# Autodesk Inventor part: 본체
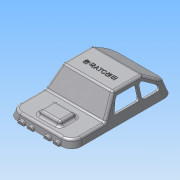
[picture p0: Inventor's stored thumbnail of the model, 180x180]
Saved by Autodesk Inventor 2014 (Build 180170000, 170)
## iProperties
Created: 2015-05
Part Number: 본체
Material: ABS 플라스틱
Document SubType Name: Modeling
Designer: Administrator
Density: 1.06 g/cm^3
Appearance: 매끄러움 - 흰색
Mass: 31 g
Surface Area: 297.951 cm^2
Volume: 29.2452 cm^3
Author: Administrator
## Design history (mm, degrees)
sketch "스케치1"
  geometry: 1 further point
sketch "스케치2"
  geometry: L1 (-61, -38)-(61, -38); L2 (61, -38)-(61, 38); L3 (61, 38)-(-61, 38); L4 (-61, 38)-(-61, -38); L5 (-61, -38)-(61, 38); L6 (61, -38)-(-61, 38); 1 further point
  constraints: 12 end point, 2 midpoint, 2 parallel, 1 horizontal, 1 perpendicular
  dimensions: "d0" = 122 distance of L2.end L3.end; "d1" = 76 distance of L1.end L2.end
extrude "돌출1" new body sketch "스케치2" distance "d2" = 30; taper "d3" = -15 deg
fillet "모깎기1" dims "d4" = 12
sketch "스케치3"
  geometry: L1 (31, 30)-(63.58, 8.28); L2 (41.37, 30)-(52.962, 30) reference; L3 (-41.37, 30)-(41.37, 30) reference; L4 (31, 30)-(52.962, 30); L5 (61, 0)-(49.409, 0) reference; L6 (61, 0)-(61, 30.779); L7 (52.962, 30)-(61, 0) reference; L8 (52.962, 30)-(57.738, 12.175); L9 (52.962, 30)-(57.738, 12.175); 2 further points
  constraints: 10 end point, 4 point on line, 3 collinear, 1 coincident, 1 perpendicular
  dimensions: "d45" = 20 distance from line of L3 point (61, 10); "d53" = 30 horizontal distance of L1.start L5.start
extrude "돌출2" cut sketch "스케치3" stored distance "d7" = 30; taper "d8" = 0 deg
sketch "스케치4"
  geometry: L1 (-41.37, 30)-(31, 30) reference; L2 (-52.962, 30)-(-41.37, 30) reference; L3 (-61, 0)-(-52.962, 30) reference; L4 (-49.409, 0)-(-61, 0) reference; L5 (49.409, 0)-(-49.409, 0) reference; L6 (-3.595, 30)-(-19, 8); L7 (-19, 8)-(-58.856, 8); L8 (-61, 0)-(-58.856, 8); 1 further point
  constraints: 6 end point, 3 point on line, 1 parallel
  dimensions: "d9" = 42 horizontal distance of L6.end L3.start; "d10" = 125 deg angle of L6 L7; "d11" = 8 distance between parallel lines of L4 L7; "d29" = 105 deg angle of L4 L8
extrude "돌출3" cut sketch "스케치4" stored distance "d12" = 30; taper "d13" = 0 deg
sketch "스케치5"
  geometry: L1 (11, -22.856)-(31, -22.856); L2 (31, -22.856)-(31, -48.856); L3 (31, -48.856)-(11, -48.856); L4 (11, -48.856)-(11, -22.856); L5 (42, -62.265)-(42, -9.448) reference; 2 further points
  constraints: 8 end point, 2 parallel, 1 horizontal, 1 horizontal alignment, 1 midpoint, 1 perpendicular
  dimensions: "d14" = 11 distance between parallel lines of L2 L5; "d15" = 20 distance between parallel lines of L4 L2; "d16" = 26 distance of L3.end L1.start
extrude "돌출4" join sketch "스케치5" distance "d17" = 5; taper "d18" = 0 deg
fillet "모깎기2" dims "d19" = 3
fillet "모깎기3" dims "d20" = 3
node "작업 평면1"
sketch "스케치10"
  geometry: A1 r 4 centre (-10, 0) between (-6, 0) and (-14, 0); A2 r 4 centre (-21, 0) between (-17, 0) and (-25, 0); 4 further points
  constraints: 4 point on circle, 2 centre point, 2 horizontal alignment, 8 other
  dimensions: "d31" = 8 diameter of A1; "d32" = 8 diameter of A2; "d33" = 11 distance of A2.centre A1.centre; "d34" = 10 distance of A1.centre point (0, 0)
extrude "돌출6" join sketch "스케치10" stored distance "d35" = 2; taper "d36" = 0 deg
fillet "모깎기5" dims "d37" = 1
fillet "모깎기6" dims "d52" = 3
sketch "스케치17"
  geometry: L1 (-18.104, 9.279)-(-4.491, 28.721) reference; L2 (-2.034, 30)-(30.092, 30) reference; L3 (31.756, 29.496)-(46.213, 19.858) reference; L4 (-8.19, 14.721)-(-1.888, 23.721); L5 (0.569, 25)-(19.504, 25); L6 (-5.733, 10)-(19.504, 10); L7 (22.504, 13)-(22.504, 22); L8 (30.242, 24.496)-(45.334, 14.435); L9 (25.578, 22)-(25.578, 11.939); L10 (28.578, 8.939)-(43.669, 8.939); A1 r 3 centre (-5.733, 13) between (-8.19, 14.721) and (-5.733, 10); A2 r 3 centre (0.569, 22) between (0.569, 25) and (-1.888, 23.721); A3 r 3 centre (19.504, 22) between (22.504, 22) and (19.504, 25); A4 r 3 centre (19.504, 13) between (19.504, 10) and (22.504, 13); A5 r 3 centre (43.669, 11.939) between (43.669, 8.939) and (45.334, 14.435); A6 r 3 centre (28.578, 22) between (30.242, 24.496) and (25.578, 22); A7 r 3 centre (28.578, 11.939) between (25.578, 11.939) and (28.578, 8.939); 8 further points
  constraints: 14 end point, 14 point on circle, 14 tangent, 12 point on line, 7 centre point, 5 equal radius, 5 parallel, 2 perpendicular, 1 horizontal alignment, 1 midpoint
  dimensions: "d54" = 5 distance between parallel lines of L1 L4; "d55" = 5 distance between parallel lines of L2 L5; "d56" = 34 distance of point (-11.496, 10) point (22.504, 10); "d61" = 15 distance of point (22.504, 10) point (22.504, 25); "d72" = 3 radius of A1; "d104" = 5 distance between parallel lines of L3 L8; "d105" = 28 distance of point (53.578, 8.939) point (25.578, 8.939); "d106" = 3 radius of A5
feature "쉘1" dims "d73" = 2
extrude "돌출8" cut sketch "스케치17" stored distance "d74" = 2; taper "d75" = 0 deg
sketch "스케치18"
  geometry: L1 (-5, 21)-(5, 21); L2 (5, 21)-(5, 23); L3 (5, 23)-(-5, 23); L4 (-5, 23)-(-5, 21); L5 (-5, 21)-(5, 23); L6 (5, 21)-(-5, 23); L7 (-5, -23)-(5, -23); L8 (5, -23)-(5, -21); L9 (5, -21)-(-5, -21); L10 (-5, -21)-(-5, -23); L11 (-5, -23)-(5, -21); L12 (5, -23)-(-5, -21); L13 (-45, -1)-(-35, -1); L14 (-35, -1)-(-35, 1); L15 (-35, 1)-(-45, 1); L16 (-45, 1)-(-45, -1); L17 (-45, -1)-(-35, 1); L18 (-35, -1)-(-45, 1); L19 (35, -1)-(45, -1); L20 (45, -1)-(45, 1); L21 (45, 1)-(35, 1); L22 (35, 1)-(35, -1); L23 (35, -1)-(45, 1); L24 (45, -1)-(35, 1); C1 r 3 at (40, 0); C2 r 3 at (0, 22); C3 r 3 at (0, -22); C4 r 3 at (-40, 0); 1 further point
  constraints: 48 end point, 8 midpoint, 8 parallel, 4 centre point, 4 horizontal, 4 perpendicular, 2 horizontal alignment, 2 vertical alignment
  dimensions: "d76" = 6 diameter of C3; "d77" = 6 diameter of C1; "d78" = 6 diameter of C2; "d79" = 6 diameter of C4; "d80" = 10 distance of L2.end L3.end; "d81" = 22 distance of C3.centre point (0, 0); "d82" = 22 distance of C2.centre point (0, 0); "d83" = 2 distance of L1.end L2.end; "d88" = 40 horizontal distance of C1.centre C3.centre; "d89" = 40 horizontal distance of C3.centre C4.centre; "d93" = 10 distance of L8.end L9.end; "d94" = 2 distance of L7.end L8.end; "d95" = 10 distance of L14.end L15.end; "d96" = 2 distance of L13.end L14.end; "d97" = 10 distance of L20.end L21.end; "d98" = 2 distance of L19.end L20.end
sketch "스케치24"
  geometry: L1 (-61, 26.409)-(-61, -26.409) reference; 2 further points
  constraints: 1 other
  dimensions: "d90" = 50 distance from line of point (-11, 0.364) L1
feature "엠보싱1" sketch "스케치24" dims "d0" = 122, "d1" = 76, "d91" = 0.5, "d92" = 0
extrude "돌출11" cut sketch "스케치17" stored distance "d107" = 10; taper "d108" = 0 deg
extrude "돌출12" join sketch "스케치18" stored distance "d109" = 10; taper "d110" = 2 deg
hole "구멍1" diameter "d113" = 3.242; stored, may be unused: countersink angle "d117" = 90 deg, drill point angle "d119" = 118 deg; dims "d111" = 10, "d112" = 10, "d114" = 9, "d115" = 4, "d116" = 2, "d118" = 11
hole "구멍2" diameter "d122" = 3.242; stored, may be unused: countersink angle "d126" = 90 deg, drill point angle "d128" = 118 deg; dims "d120" = 10, "d121" = 10, "d123" = 9, "d124" = 4, "d125" = 2, "d127" = 11
hole "구멍3" diameter "d131" = 3.242; stored, may be unused: countersink angle "d135" = 90 deg, drill point angle "d137" = 118 deg; dims "d129" = 10, "d130" = 10, "d132" = 9, "d133" = 4, "d134" = 2, "d136" = 11
hole "구멍4" diameter "d140" = 3.242; stored, may be unused: countersink angle "d144" = 90 deg, drill point angle "d146" = 118 deg; dims "d138" = 10, "d139" = 10, "d141" = 9, "d142" = 4, "d143" = 2, "d145" = 11
node "솔리드1"
mirror "대칭1"
other parameters: "d30" = 63
